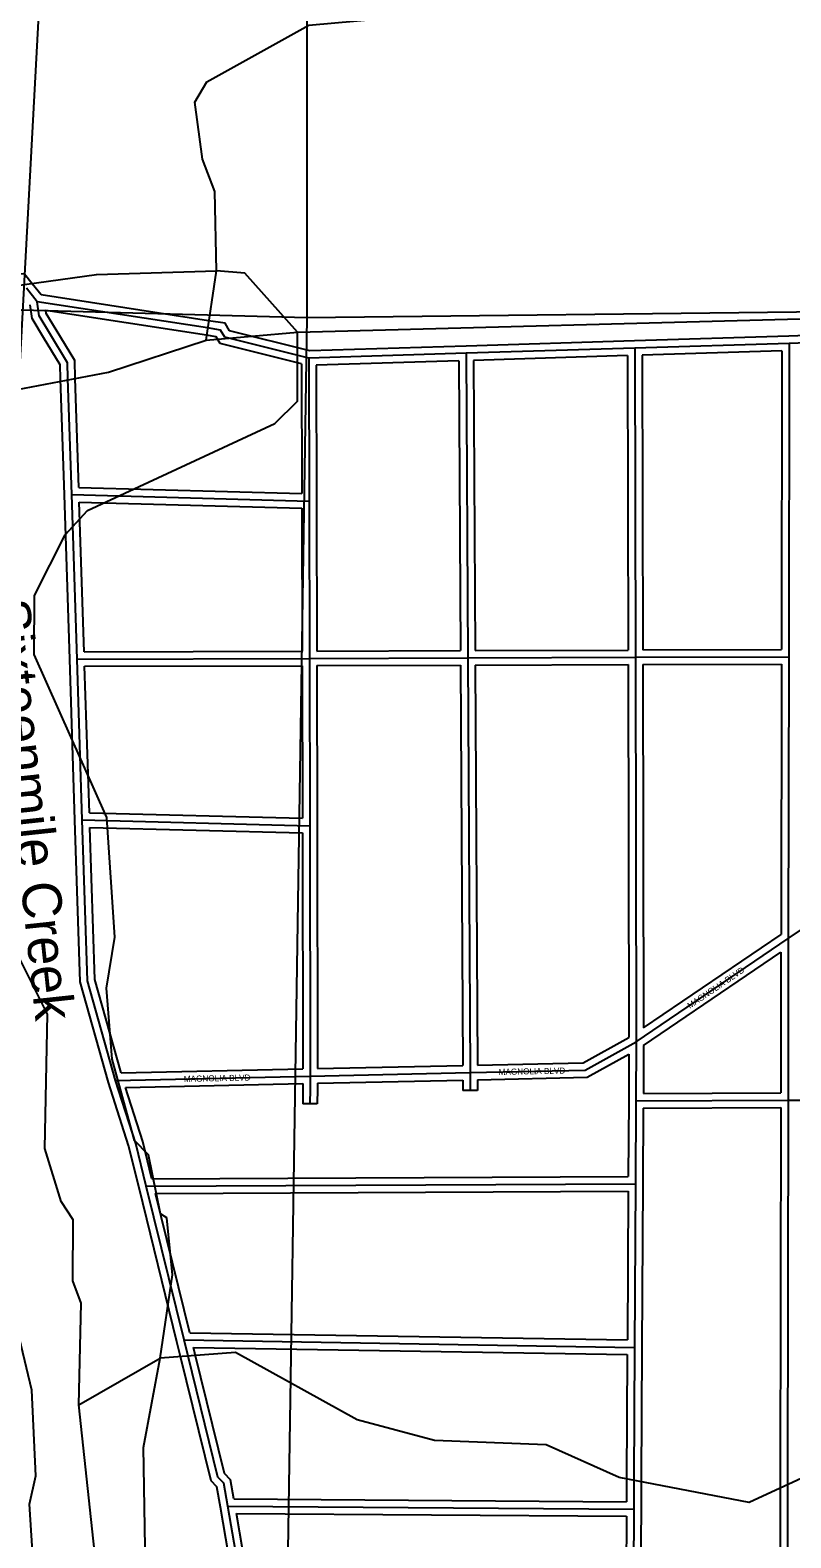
# Model space of a CAD drawing. Extents: x 418523 to 616617, y 1878279 to 2196743.
# Drawn here: x 509805 to 512924, y 1934208 to 1940391 of the extents above; entities that cross this region are included whole.
import ezdxf

# ---------------------------------------------------------------- set-up
doc = ezdxf.new("R2010")
doc.units = 0
for name, color, linetype in [('Level 1', 7, 'Continuous'), ('Level 31', 7, 'Continuous'), ('Level 32', 7, 'Continuous'), ('Level 34', 7, 'Continuous'), ('Level 41', 7, 'Continuous'), ('Level 5', 7, 'Continuous'), ('Level 7', 7, 'Continuous')]:
    doc.layers.add(name, color=color, linetype=linetype)

msp = doc.modelspace()

# ---------------------------------------------------------------- linework, layer by layer
at = {"layer": 'Level 1'}
for p, q in [((510082, 1944971.906), (509725.664, 1938346.524)), ((510936.339, 1944443.711), (510939.835, 1939212.011)), ((505545.598, 1939359.515), (510939.835, 1939212.011)), ((510939.835, 1939212.011), (516246.208, 1939273.459)), ((510939.835, 1939212.011), (510855.55, 1933798.987))]:
    msp.add_line(p, q, dxfattribs=at)
at = {"layer": 'Level 31'}
for p, q in [((509833.749, 1939277.471), (509790.136, 1939332.556)), ((510532.067, 1939169.611), (509833.749, 1939277.471)), ((510947.973, 1939046.509), (510603.698, 1939131.507)), ((512917.087, 1939106.445), (512284.329, 1939087.09)), ((512917.087, 1939106.445), (512915.594, 1937821.294)), ((513570.81, 1939126.457), (512917.087, 1939106.445)), ((511593.12, 1939065.792), (510947.973, 1939046.509)), ((510947.973, 1939046.509), (510949.16, 1938459.927)), ((512284.329, 1939087.09), (511593.12, 1939065.792)), ((511593.12, 1939065.792), (511599.98, 1937816.611)), ((512284.329, 1939087.09), (512287.009, 1937819.014)), ((509975.448, 1938486.686), (509959.861, 1938962.046)), ((509975.448, 1938486.686), (510949.16, 1938459.927)), ((509997.55, 1937812.017), (509975.448, 1938486.686)), ((510949.16, 1938459.927), (510950.433, 1937814.798)), ((509997.55, 1937812.017), (510950.433, 1937814.798)), ((510018.761, 1937152.262), (509997.55, 1937812.017)), ((510950.433, 1937814.798), (511599.98, 1937816.611)), ((510950.433, 1937814.798), (510951.86, 1937127.848)), ((511599.98, 1937816.611), (512287.009, 1937819.014)), ((511599.98, 1937816.611), (511608.885, 1936115.761)), ((512287.009, 1937819.014), (512915.594, 1937821.294)), ((512287.009, 1937819.014), (512290.076, 1936242.195)), ((512915.594, 1937821.294), (512913.655, 1936666.334)), ((510018.761, 1937152.262), (510951.86, 1937127.848)), ((510951.86, 1937127.848), (510953.223, 1936101.245)), ((512913.655, 1936666.334), (513572.253, 1937115.077)), ((512290.076, 1936242.195), (512913.655, 1936666.334)), ((512913.655, 1936666.334), (512912.986, 1936002.667)), ((512290.076, 1936242.195), (512289.134, 1936000.368)), ((510155.245, 1936083.667), (510953.223, 1936101.245)), ((510953.223, 1936101.245), (511608.885, 1936115.761)), ((511608.885, 1936115.761), (511609.235, 1936042.665)), ((512289.134, 1936000.368), (512287.173, 1935659.995)), ((512289.134, 1936000.368), (512912.986, 1936002.667)), ((512912.986, 1936002.667), (512910.38, 1934429.871)), ((512912.986, 1936002.667), (513573.05, 1936005.201)), ((510280.905, 1935650.057), (512287.173, 1935659.995)), ((510435.967, 1935019.229), (510280.905, 1935650.057)), ((512287.173, 1935659.995), (512283.605, 1934988.701)), ((510450.973, 1934958.076), (510435.967, 1935019.229)), ((510435.967, 1935019.229), (512283.605, 1934988.701)), ((512283.605, 1934988.701), (512280.22, 1934446.142)), ((512280.22, 1934446.142), (512279.751, 1934325.775)), ((512910.38, 1934429.871), (512909.801, 1933871.301)), ((510615.295, 1934338.123), (512279.751, 1934325.775)), ((512279.751, 1934325.775), (512276.974, 1933857.399))]:
    msp.add_line(p, q, dxfattribs=at)
for points in [[(509885.636, 1939146.713), (509841.775, 1939219.255), (509833.749, 1939277.471)], [(510603.698, 1939131.507), (510586.03, 1939161.396), (510532.067, 1939169.611)], [(509959.861, 1938962.046), (509957.895, 1939027.148), (509885.636, 1939146.713)], [(510155.245, 1936083.667), (510039.973, 1936492.508), (510018.761, 1937152.262)], [(511608.885, 1936115.761), (512081.254, 1936126.276), (512290.076, 1936242.195)], [(510280.905, 1935650.057), (510237.761, 1935824.782), (510155.245, 1936083.667)], [(510953.223, 1936101.245), (510953.019, 1936049.243), (510952.457, 1935987.423)], [(510615.295, 1934338.123), (510599.145, 1934431.283), (510574.15, 1934456.474), (510450.973, 1934958.076)], [(510747.321, 1933824.122), (510648.215, 1934147.438), (510615.295, 1934338.123)]]:
    msp.add_lwpolyline(points, dxfattribs=at)
at = {"layer": 'Level 32'}
for p, q in [((509849.963, 1939305.322), (509813.659, 1939351.178)), ((510536.647, 1939199.259), (509849.963, 1939305.323)), ((510527.489, 1939139.961), (509868.97, 1939241.673)), ((510951.18, 1939076.618), (510623.116, 1939157.614)), ((513569.892, 1939156.444), (512916.169, 1939136.431)), ((510918.02, 1939023.001), (510584.281, 1939105.399)), ((511592.196, 1939095.778), (510951.179, 1939076.618)), ((512283.405, 1939117.076), (511592.196, 1939095.778)), ((512916.17, 1939136.431), (512283.411, 1939117.076)), ((511563.29, 1939034.886), (510978.033, 1939017.392)), ((511563.289, 1939034.886), (511569.815, 1937846.526)), ((512254.395, 1939056.151), (511623.282, 1939036.706)), ((511623.282, 1939036.706), (511629.816, 1937846.715)), ((512254.395, 1939056.151), (512256.946, 1937848.909)), ((512314.391, 1939057.993), (512316.946, 1937849.123)), ((512887.051, 1939075.511), (512314.392, 1939057.993)), ((512887.052, 1939075.511), (512885.63, 1937851.186)), ((510918.021, 1939023.001), (510919.097, 1938490.766)), ((510978.033, 1939017.392), (510979.16, 1938459.988)), ((509945.464, 1938485.702), (509929.877, 1938961.061)), ((510004.507, 1938515.899), (509989.849, 1938962.951)), ((509967.566, 1937811.035), (509945.464, 1938485.703)), ((510004.508, 1938515.899), (510919.097, 1938490.766)), ((510006.476, 1938455.821), (510919.216, 1938430.737)), ((510026.582, 1937842.103), (510006.476, 1938455.821)), ((510919.217, 1938430.737), (510920.374, 1937844.711)), ((510979.16, 1938459.986), (510980.375, 1937844.882)), ((512316.946, 1937849.123), (512885.629, 1937851.186)), ((509988.776, 1937151.298), (509967.565, 1937811.053)), ((510026.582, 1937842.102), (510920.374, 1937844.711)), ((510980.375, 1937844.882), (511569.815, 1937846.526)), ((511629.816, 1937846.715), (512256.946, 1937848.909)), ((512317.069, 1937789.121), (512319.968, 1936298.807)), ((512317.07, 1937789.121), (512885.544, 1937791.184)), ((512885.544, 1937791.184), (512883.682, 1936682.229)), ((510028.529, 1937782.106), (510920.495, 1937784.71)), ((510047.838, 1937181.512), (510028.529, 1937782.106)), ((510920.495, 1937784.709), (510921.796, 1937158.646)), ((510980.496, 1937784.881), (511570.136, 1937786.526)), ((510980.496, 1937784.881), (510981.86, 1937127.911)), ((511570.137, 1937786.526), (511578.731, 1936145.101)), ((511630.139, 1937786.714), (512257.068, 1937788.908)), ((511630.139, 1937786.714), (511638.725, 1936146.432)), ((512257.068, 1937788.907), (512260.043, 1936259.834)), ((510047.838, 1937181.512), (510921.796, 1937158.646)), ((510049.769, 1937121.44), (510921.898, 1937098.621)), ((510981.86, 1937127.888), (510983.183, 1936131.916)), ((510921.899, 1937098.62), (510923.184, 1936130.59)), ((512319.968, 1936298.807), (512883.681, 1936682.229)), ((512320.016, 1936226.275), (512883.598, 1936609.606)), ((512883.599, 1936609.606), (512883.016, 1936032.556)), ((512259.878, 1936191.116), (512259.135, 1936000.484)), ((512320.015, 1936226.275), (512319.254, 1936030.479)), ((510177.815, 1936114.171), (510923.184, 1936130.59)), ((510983.184, 1936131.916), (511578.731, 1936145.101)), ((510196.013, 1936054.556), (510923.103, 1936070.571)), ((510983.11, 1936071.896), (511579.031, 1936085.091)), ((511579.031, 1936085.091), (511579.235, 1936042.521)), ((511639.027, 1936086.423), (511639.235, 1936042.808)), ((511639.235, 1936042.808), (511579.235, 1936042.521)), ((512259.135, 1936000.541), (512257.344, 1935689.848)), ((512319.254, 1936030.479), (512883.015, 1936032.556)), ((510982.457, 1935987.151), (510922.457, 1935987.696)), ((512318.964, 1935970.476), (512317.173, 1935659.821)), ((512318.965, 1935970.476), (512882.936, 1935972.555)), ((512882.936, 1935972.555), (512880.38, 1934429.921)), ((510304.371, 1935680.173), (512257.345, 1935689.848)), ((510406.834, 1935012.068), (510251.773, 1935642.896)), ((510319.128, 1935620.244), (512257.012, 1935629.844)), ((512257.013, 1935629.843), (512253.767, 1935019.198)), ((512317.173, 1935659.836), (512313.605, 1934988.542)), ((510459.582, 1935048.843), (510319.128, 1935620.244)), ((510421.837, 1934950.926), (510406.831, 1935012.08)), ((510459.582, 1935048.844), (512253.767, 1935019.199)), ((510480.109, 1934965.226), (510474.376, 1934988.589)), ((510474.377, 1934988.589), (512253.42, 1934959.195)), ((512253.42, 1934959.195), (512250.22, 1934446.33)), ((512313.605, 1934988.514), (512310.22, 1934445.955)), ((512250.22, 1934446.259), (512249.87, 1934355.996)), ((512310.22, 1934446.026), (512309.752, 1934325.657)), ((512880.38, 1934429.901), (512879.801, 1933871.331)), ((510640.575, 1934367.936), (512249.87, 1934355.997)), ((510650.965, 1934307.856), (512249.575, 1934295.996)), ((512249.575, 1934295.997), (512246.975, 1933857.576)), ((512309.752, 1934325.596), (512306.975, 1933857.22))]:
    msp.add_line(p, q, dxfattribs=at)
for points in [[(509813.567, 1939351.293), (509782.475, 1939390.173), (509579.17, 1939402.188)], [(509859.964, 1939131.191), (509812.901, 1939209.027), (509805.148, 1939265.266)], [(509911.309, 1939162.236), (509870.65, 1939229.482), (509868.969, 1939241.674)], [(509989.849, 1938962.951), (509987.645, 1939035.925), (509911.312, 1939162.231)], [(510623.116, 1939157.614), (510604.614, 1939188.914), (510536.647, 1939199.259)], [(509929.874, 1938961.14), (509928.146, 1939018.371), (509859.96, 1939131.196)], [(510584.281, 1939105.399), (510567.445, 1939133.879), (510527.553, 1939139.951)], [(510126.509, 1936075.038), (510010.105, 1936487.888), (509988.776, 1937151.299)], [(510177.816, 1936114.171), (510069.84, 1936497.129), (510049.769, 1937121.44)], [(511638.726, 1936146.433), (512073.175, 1936156.105), (512260.042, 1936259.834)], [(511639.027, 1936086.422), (512089.333, 1936096.448), (512259.878, 1936191.117)], [(510251.78, 1935642.865), (510208.875, 1935816.621), (510126.509, 1936075.038)], [(510923.103, 1936070.571), (510923.019, 1936049.439), (510922.457, 1935987.696)], [(510983.109, 1936071.897), (510983.019, 1936049.048), (510982.457, 1935987.151)], [(510304.371, 1935680.174), (510266.649, 1935832.942), (510196.013, 1936054.556)], [(510585.735, 1934332.999), (510571.197, 1934416.855), (510546.997, 1934441.245), (510421.838, 1934950.921)], [(510640.575, 1934367.936), (510627.091, 1934445.711), (510601.301, 1934471.703), (510480.107, 1934965.231)], [(510718.638, 1933815.33), (510618.975, 1934140.463), (510585.732, 1934333.02)], [(510776.004, 1933832.915), (510677.455, 1934154.414), (510650.965, 1934307.856)]]:
    msp.add_lwpolyline(points, dxfattribs=at)
at = {"layer": 'Level 5'}
for p, q in [((510526.546, 1939120.368), (510569.142, 1939403.676)), ((510901.784, 1939152.504), (516245.868, 1939293.737)), ((510526.546, 1939120.368), (510901.784, 1939152.504)), ((510004.035, 1934753.75), (510338.108, 1934944.439)), ((510101.193, 1933853.131), (510004.035, 1934753.75))]:
    msp.add_line(p, q, dxfattribs=at)
for points in [[(510569.142, 1939403.676), (510561.856, 1939728.823), (510512.263, 1939862.366), (510479.668, 1940095.891), (510529.947, 1940179.083), (510947.512, 1940411.164), (511923.162, 1940499.728), (512106.357, 1940440.78), (512264.82, 1940465.302), (512565.514, 1940647.721), (512774.087, 1940697.084), (513407.78, 1940728.373), (513549.752, 1940811.307), (513633.511, 1940936.061), (513631.934, 1943045.19)], [(509608.8, 1938889.891), (510125.98, 1938988.26), (510526.546, 1939120.368)], [(510004.035, 1934753.75), (510013.707, 1935170.57), (509980.655, 1935262.371), (509981.47, 1935512.457), (509931.678, 1935587.648), (509865.672, 1935804.592), (509875.772, 1936354.756), (509710.123, 1936688.771)], [(515014.759, 1934929.41), (514447.697, 1934864.551), (513939.107, 1934841.173), (513830.864, 1934883.213), (513597.32, 1934850.619), (512987.524, 1934460.742), (512753.75, 1934353.116), (512220.547, 1934454.892), (511920.868, 1934589.221), (511462.438, 1934607.366), (511145.91, 1934691.733), (510646.614, 1934968.443), (510338.108, 1934944.439)]]:
    msp.add_lwpolyline(points, dxfattribs=at)
at = {"layer": 'Level 7'}
for points in [[(509485.09, 1939307.099), (510077.232, 1939388.568), (510569.142, 1939403.676)], [(510901.784, 1939152.504), (510685.825, 1939394.946), (510569.142, 1939403.676)], [(510338.108, 1934944.439), (510389.203, 1935286.067), (510364.938, 1935519.552), (510339.997, 1935536.322), (510290.762, 1935778.207), (510232.57, 1935836.758), (510141.951, 1936170.505), (510117.885, 1936462.381), (510151.883, 1936670.656), (510120.143, 1937162.637), (509822.155, 1937830.489), (509822.94, 1938072.245), (509948.768, 1938321.942), (510040.789, 1938421.686), (510808.879, 1938777.664), (510900.869, 1938869.067), (510901.784, 1939152.504)], [(509834.437, 1933853.987), (509802.657, 1934345.928), (509828.025, 1934462.571), (509812.489, 1934812.729), (509746.683, 1935088.055), (509680.25, 1935171.616), (509647.884, 1935471.852), (509622.913, 1935488.592), (509598.589, 1935697.066), (509573.647, 1935722.177), (509516.141, 1935989.132), (509459.54, 1936539.494)], [(510334.479, 1933810.702), (510343.117, 1933910.705), (510301.625, 1933969.186), (510277.27, 1934169.33), (510270.243, 1934577.84), (510338.108, 1934944.439)]]:
    msp.add_lwpolyline(points, dxfattribs=at)

# ---------------------------------------------------------------- texts
at = {"layer": 'Level 34'}
for rotation, p in [(34.2214972, (512510.451, 1936376.972)), (1.27455, (511726.322, 1936105.875)), (1.26115, (510435.483, 1936077.339))]:
    msp.add_text('MAGNOLIA BLVD', height=25, rotation=rotation, dxfattribs=at).set_placement(p)
at = {"layer": 'Level 41'}
msp.add_text('Sixteenmile Creek', height=160, rotation=276.1318, dxfattribs=at).set_placement((509641.676, 1938050.613))

doc.saveas('drawing.dxf')
